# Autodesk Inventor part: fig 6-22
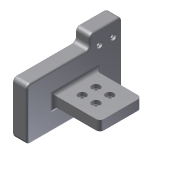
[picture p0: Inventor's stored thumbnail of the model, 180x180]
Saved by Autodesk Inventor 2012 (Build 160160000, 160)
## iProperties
Created: 2004-05
Part Number: fig 6-22
Document SubType Name: Modeling
Designer: CADCIM Technologies
Manufacturer: Standard
Standards Organization: Custom
Density: 1 g/cm^3
Material: Default
Author: CADCIM Technologies
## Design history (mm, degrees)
node "Sketch1"
sketch "Sketch2"
  geometry: L1 (0, 0)-(0, 26.557); L2 (0, 26.557)-(31.986, 26.557); L3 (31.986, 26.557)-(31.986, 32.916); L4 (31.986, 32.916)-(48.42, 32.916); L5 (48.42, 32.916)-(48.42, 0); L6 (48.42, 0)-(0, 0)
  constraints: 12 end point, 4 parallel, 1 perpendicular, 1 vertical
extrude "Extrusion1" new body sketch "Sketch2" distance "d0" = 7.5; taper "d1" = 0 deg
workplane "Work Plane1"
sketch "Sketch3"
  geometry: L1 (7.5, 35.088)-(30.78, 35.088); L2 (30.78, 35.088)-(30.78, 13.871); L3 (30.78, 13.871)-(7.5, 13.871); L4 (7.5, 31.986)-(7.5, 48.42) reference; L5 (7.5, 0)-(7.5, 31.986) reference
  constraints: 6 end point, 2 point on line, 1 horizontal, 1 parallel, 1 perpendicular
extrude "Extrusion2" join sketch "Sketch3" distance "d3" = 5; taper "d4" = 0 deg
fillet "Fillet2" dims "d7" = 2
fillet "Fillet3" dims "d8" = 2
hole "Hole1" diameter "d11" = 3; stored, may be unused: countersink angle "d15" = 90 deg, drill point angle "d17" = 118 deg; dims "d9" = 7, "d10" = 16, "d12" = 6, "d13" = 4, "d14" = 2, "d16" = 8
pattern_linear "Rectangular Pattern1" dims "d20" = 7, "d23" = 7
hole "Hole2" diameter "d26" = 2; stored, may be unused: countersink angle "d30" = 90 deg, drill point angle "d32" = 118 deg; dims "d24" = 5, "d25" = 7, "d27" = 6, "d28" = 3, "d29" = 1, "d31" = 8
pattern_linear "Rectangular Pattern2" dims "d35" = 7
fillet "Fillet4" dims "d36" = 2
fillet "Fillet5" dims "d37" = 1
fillet "Fillet6" dims "d38" = 1
body "Solid1"
other parameters: "d2" = -11
